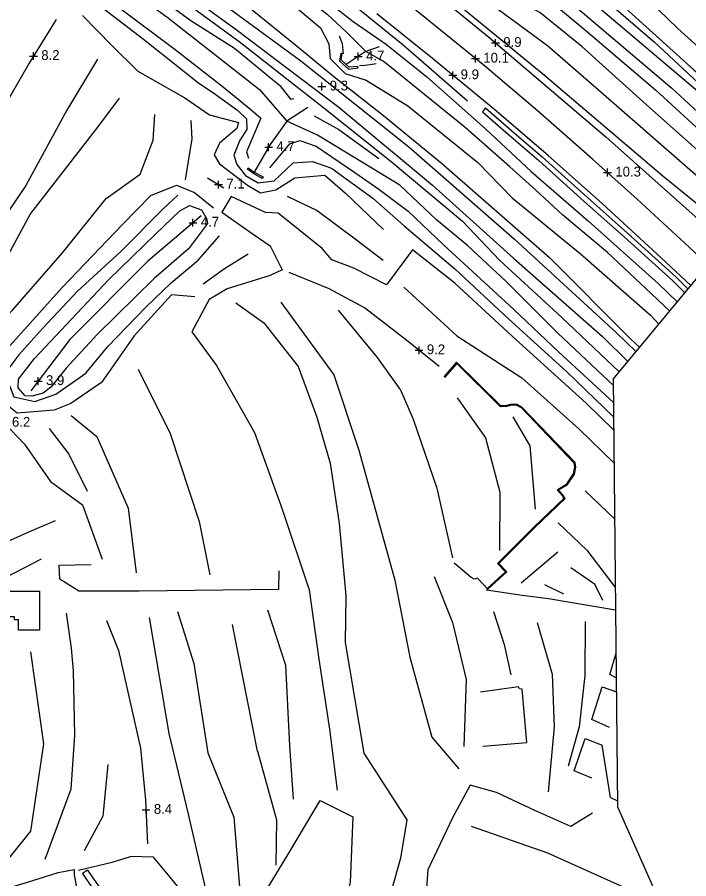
# Model space of a CAD drawing. Extents: x 2316231 to 2323598, y 363169 to 371906.
# Drawn here: x 2320503.7 to 2320845.6, y 365317.1 to 365756.1 of the extents above; entities that cross this region are included whole.
import ezdxf

# ---------------------------------------------------------------- set-up
doc = ezdxf.new("R2010")
doc.units = 0
for name, color, linetype in [('RD_DTM_BkLn1', 7, 'Continuous'), ('RD_DTM_TinHull', 7, 'Continuous'), ('RD_DTM_Void', 7, 'Continuous'), ('RD_EX_H2O', 7, 'Continuous'), ('RD_EX_Road', 7, 'Continuous')]:
    doc.layers.add(name, color=color, linetype=linetype)

msp = doc.modelspace()

# ---------------------------------------------------------------- linework, layer by layer
at = {"layer": 'RD_DTM_BkLn1'}
for p, q in [((2320600.584, 365674.209), (2320608.887, 365669.095)), ((2320778.886, 365483.504), (2320760.207, 365467.735)), ((2320781.977, 365462.194), (2320772.252, 365466.971)), ((2320626.054, 365382.15), (2320613.359, 365446.643)), ((2320732.239, 365418.613), (2320731.107, 365384.51)), ((2320789.848, 365394.629), (2320784.128, 365374.551)), ((2320805.686, 365358.613), (2320801.488, 365385.269)), ((2320805.686, 365358.613), (2320809.333, 365356.823))]:
    msp.add_line(p, q, dxfattribs=at)
for points in [[(2320125.425, 366145.994), (2320161.294, 366129.015), (2320184.806, 366118.194), (2320219.268, 366097.334), (2320257.75, 366078.61), (2320301.401, 366053.593), (2320339.6, 366032.049), (2320388.854, 366006.136), (2320433.491, 365980.54), (2320471.094, 365961.437), (2320509.936, 365935.57), (2320558.33, 365906.04), (2320596.656, 365879.53), (2320637.36, 365850.344), (2320679.307, 365816.521), (2320703.841, 365798.525), (2320711.978, 365788.521), (2320716.795, 365779.622), (2320731.36, 365769.609), (2320746.226, 365761.92), (2320773.664, 365741.714), (2320802.121, 365716.946), (2320848.849, 365676.056), (2320875.469, 365654.227)], [(2320183.14, 366148.693), (2320239.09, 366117.639), (2320296.494, 366085.739), (2320349.802, 366055.132), (2320405.378, 366025.418), (2320448.083, 365999.362), (2320490.768, 365974.618), (2320559.324, 365931.873), (2320617.279, 365892.959), (2320678.148, 365848.809), (2320727.47, 365811.314), (2320779.04, 365769.194), (2320836.996, 365719.869), (2320889.686, 365671.382)], [(2320182.737, 366143.817), (2320231.045, 366116.001), (2320278.866, 366087.979), (2320328.405, 366059.321), (2320373.611, 366034.853), (2320417.281, 366010.392), (2320460.243, 365986.01), (2320498.805, 365963.232), (2320547.113, 365932.568), (2320590.276, 365902.488), (2320625.131, 365879.992), (2320670.35, 365847.996), (2320704.214, 365820.962), (2320721.604, 365807.145), (2320731.665, 365799.894), (2320745.055, 365790.38), (2320759.08, 365777.797), (2320794.333, 365748.347), (2320828.782, 365718.919), (2320859.537, 365690.73), (2320885.477, 365666.303)], [(2320232.419, 366129.527), (2320276.765, 366104.361), (2320326.97, 366076.072), (2320377.845, 366047.504), (2320438.873, 366013.35), (2320491.432, 365981.475), (2320553.439, 365943.338), (2320618.359, 365900.899), (2320682.218, 365854.928), (2320740.085, 365810.827), (2320800.745, 365760.357), (2320857.803, 365711.976), (2320894.516, 365677.21)], [(2320320.221, 366098.87), (2320343.73, 366084.834), (2320356.505, 366077.219), (2320384.555, 366059.676), (2320419.447, 366040.181), (2320447.866, 366021.901), (2320471.868, 366008.615), (2320488.936, 365996.515), (2320514.303, 365982.74), (2320529.316, 365972.626), (2320554.954, 365955.917), (2320587.739, 365935.149), (2320612.576, 365918.662), (2320641.664, 365897.147), (2320678.381, 365870.456), (2320716.77, 365840.459), (2320734.571, 365828.326), (2320756.632, 365810.066), (2320790.938, 365779.493), (2320809.818, 365763.92), (2320848.173, 365729.232), (2320863.138, 365716.2), (2320899.36, 365685.757), (2320900.62, 365684.576)], [(2320315.308, 366088.614), (2320345.863, 366070.993), (2320387.782, 366047.357), (2320430.265, 366024.388), (2320470.415, 366003.883), (2320504.878, 365981.214), (2320529.854, 365965.458), (2320578.485, 365933.231), (2320618.03, 365906.824), (2320639.032, 365893.635), (2320675.308, 365866.642), (2320706.175, 365841.844), (2320753.882, 365805.574), (2320792.936, 365773.891), (2320828.235, 365743.377), (2320879.989, 365695.168), (2320896.418, 365679.505)], [(2320855.357, 365629.958), (2320845.868, 365638.904), (2320819.287, 365663.389), (2320796.672, 365683.748), (2320768.394, 365708.644), (2320741.53, 365731.29), (2320709.31, 365757.523), (2320675.444, 365784.438), (2320645.131, 365807.256), (2320627.321, 365820.5), (2320607.968, 365835.099), (2320591.031, 365846.394), (2320569.199, 365861.189), (2320543.695, 365879.161)], [(2320602.629, 365865.677), (2320641.904, 365832.75), (2320690.389, 365794.379), (2320722.377, 365767.546), (2320771.111, 365727.387), (2320832.413, 365675.302), (2320868.558, 365645.887)], [(2320505.475, 365856.979), (2320520.864, 365848.587), (2320545.172, 365833.324), (2320574.899, 365813.74), (2320610.258, 365787.16), (2320641.215, 365764.842), (2320658.117, 365750.723), (2320662.317, 365742.611), (2320663.086, 365735.015), (2320670.708, 365727.381), (2320681.36, 365723.951), (2320702.529, 365710.89), (2320738.215, 365682.049), (2320755.731, 365664.117), (2320790.277, 365635.787), (2320826.19, 365604.332), (2320830.311, 365599.735)], [(2320531.154, 365854.994), (2320562.66, 365836.912), (2320593.866, 365815.631), (2320622.996, 365793.667), (2320657.616, 365767.534), (2320674.76, 365753.896), (2320691.644, 365742.188), (2320712.309, 365725.73), (2320742.067, 365699.137), (2320765.35, 365677.399), (2320794.487, 365652.244), (2320830.03, 365620.462), (2320839.699, 365611.064)], [(2320494.756, 365849.313), (2320517.539, 365834.967), (2320560.151, 365809.006), (2320603.795, 365775.848), (2320645.456, 365741.875), (2320664.804, 365725.847), (2320689.325, 365706.764), (2320719.517, 365681.82), (2320774.711, 365633.699), (2320816.181, 365591.988), (2320820.585, 365587.999)], [(2320487.964, 365837.237), (2320513.325, 365820.129), (2320563.533, 365787.35), (2320615.078, 365749.886), (2320667.434, 365710.191), (2320715.063, 365670.543), (2320756.33, 365633.36), (2320801.65, 365593.339), (2320814.522, 365580.683)], [(2320495.801, 365839.314), (2320540.146, 365810.177), (2320599.875, 365769.409), (2320648.098, 365733.83), (2320703.015, 365690.061), (2320756.957, 365642.96), (2320808.871, 365595.211), (2320818.714, 365585.741)], [(2320485.487, 365833.622), (2320504.647, 365821.714), (2320535.41, 365801.833), (2320578.386, 365771.968), (2320617.431, 365743.287), (2320659.726, 365709.98), (2320694.071, 365682.621), (2320730.364, 365652.213), (2320749.321, 365632.325), (2320781.055, 365603.107), (2320810.117, 365575.367)], [(2320475.372, 365817.646), (2320481.696, 365821.632), (2320490.565, 365819.23), (2320505.711, 365810.344), (2320515.374, 365806.23), (2320528.128, 365799.749), (2320560.904, 365777.338), (2320592.16, 365754.331), (2320614.238, 365740.301), (2320637.32, 365721.378), (2320642.869, 365714.337), (2320644.444, 365714.613)], [(2320503.28, 365801.995), (2320525.612, 365785.54), (2320553.699, 365762.395), (2320584.774, 365739.166), (2320608.674, 365720.434), (2320622.584, 365709.046), (2320627.658, 365704.681), (2320620.473, 365687.552), (2320621.449, 365684.302)], [(2320654.91, 365777.105), (2320675.289, 365762.269), (2320700.245, 365742.034), (2320733.027, 365713.442)], [(2320529.506, 365774.584), (2320568.018, 365744.987), (2320596.148, 365722.409), (2320603.158, 365717.855), (2320615.924, 365708.55), (2320620.421, 365704.275), (2320620.673, 365698.871), (2320617.061, 365693.515), (2320613.976, 365685.872), (2320615.547, 365681.031), (2320619.981, 365675.493), (2320626.421, 365671.631), (2320634.495, 365672.772), (2320644.192, 365681.869), (2320653.963, 365682.658), (2320663.621, 365679.123), (2320684.68, 365663.888), (2320700.755, 365649.791), (2320726.506, 365627.952), (2320753.748, 365602.43), (2320783.313, 365575.509), (2320807.356, 365552.509)], [(2320523.577, 365754.875), (2320509.688, 365732.7), (2320480.808, 365682.431), (2320463.932, 365647.223), (2320445.882, 365607.764), (2320437.102, 365579.238), (2320429.956, 365530.993)], [(2320669.78, 365737.354), (2320669.371, 365742.512), (2320667.813, 365746.431)], [(2320544.633, 365734.641), (2320528.996, 365708.742), (2320508.038, 365670.288), (2320481.592, 365631.346), (2320476.782, 365614.234), (2320488.614, 365593.43), (2320501.486, 365606.991), (2320526.676, 365636.128), (2320548.952, 365663.705), (2320566.206, 365676.089), (2320572.957, 365693.495), (2320573.77, 365706.579)], [(2320686.439, 365732.279), (2320683.468, 365731.89), (2320680.626, 365731.406), (2320678.014, 365731.402)], [(2320555.508, 365714.842), (2320544.595, 365700.134), (2320510.509, 365656.052), (2320487.171, 365613.325)], [(2320654.935, 365705.796), (2320667.447, 365698.893), (2320687.755, 365684.07)], [(2320592.037, 365703.504), (2320592.604, 365693.949), (2320591.477, 365686.955), (2320589.121, 365673.299)], [(2320632.342, 365679.274), (2320642.504, 365691.545), (2320647.606, 365693.195), (2320655.961, 365690.385), (2320675.529, 365676.895), (2320687.857, 365668.493), (2320702.655, 365657.224), (2320720.725, 365640.16), (2320756.584, 365607.134), (2320779.29, 365585.639), (2320807.283, 365559.748)], [(2320585.385, 365665.499), (2320577.885, 365658.229), (2320556.418, 365636.81), (2320534.292, 365616.57), (2320516.697, 365597.643), (2320504.522, 365584.027), (2320497.433, 365574.637), (2320502.011, 365562.692), (2320512.57, 365560.303), (2320523.324, 365564.034), (2320538.619, 365574.788), (2320549.896, 365588.321), (2320569.229, 365608.324), (2320582.052, 365620.763), (2320595.857, 365632.327), (2320606.671, 365644.79)], [(2320641.145, 365664.925), (2320656.346, 365657.575), (2320676.463, 365642.647), (2320689.925, 365632.282)], [(2320600.555, 365650.952), (2320590.883, 365638.12), (2320573.394, 365622.986), (2320544.418, 365594.463), (2320528.664, 365577.287), (2320520.803, 365567.552), (2320516.818, 365564.505), (2320511.186, 365563.039), (2320507.713, 365563.117), (2320504.089, 365567.275), (2320504.321, 365571.644), (2320512.452, 365582.168), (2320550.307, 365622.457), (2320574.184, 365645.678), (2320586.502, 365657.472), (2320591.356, 365660.083), (2320597.581, 365657.89), (2320599.997, 365653.571), (2320600.555, 365650.952)], [(2320621.338, 365635.355), (2320609.18, 365627.895), (2320598.411, 365620.064)], [(2320718.466, 365578.11), (2320702.109, 365591.36), (2320680.513, 365608.054), (2320662.551, 365617.66), (2320642.069, 365626.081)], [(2320700.497, 365618.525), (2320727.441, 365593.74), (2320760.677, 365572.292), (2320789.569, 365546.372), (2320807.595, 365528.892)], [(2320614.91, 365610.629), (2320629.165, 365600.384), (2320646.722, 365578.161), (2320656.026, 365552.791), (2320663.046, 365528.951), (2320667.663, 365498.227), (2320670.918, 365461.504), (2320670.609, 365437.554), (2320680.119, 365381.089), (2320702.104, 365347.183)], [(2320637.827, 365610.829), (2320664.867, 365573.859), (2320677.699, 365535.552), (2320695.89, 365469.219), (2320703.524, 365430.126), (2320714.776, 365389.369), (2320728.556, 365373.232)], [(2320698.706, 365566.62), (2320687.088, 365582.706), (2320667.215, 365606.872)], [(2320592.623, 365595.722), (2320605.225, 365578.7), (2320624.488, 365544.426), (2320638.634, 365505.441), (2320652.316, 365464.288), (2320657.327, 365429.068), (2320662.604, 365393.396), (2320666.567, 365362.302)], [(2320565.209, 365576.715), (2320581.619, 365543.989), (2320596.237, 365499.125), (2320601.82, 365471.958)], [(2320698.706, 365566.62), (2320705.347, 365551.293), (2320717.365, 365516.069), (2320725.258, 365480.695)], [(2320448.075, 365556.909), (2320465.102, 365560.562), (2320481.208, 365559.511), (2320497.014, 365549.447), (2320507.384, 365538.552), (2320520.549, 365519.481), (2320536.911, 365507.637), (2320547.003, 365480.001)], [(2320727.722, 365562.148), (2320742.195, 365541.854), (2320749.366, 365514.076), (2320749.163, 365484.405)], [(2320531.084, 365553.243), (2320544.175, 365542.527), (2320560.136, 365505.966), (2320564.159, 365473.087)], [(2320756, 365552.496), (2320764.715, 365537.722), (2320767.341, 365505.498)], [(2320519.879, 365546.481), (2320529.904, 365533.439), (2320539.361, 365514.556)], [(2320792.888, 365514.836), (2320807.718, 365500.447), (2320807.884, 365500.219)], [(2320522.914, 365499.586), (2320509.013, 365493.59), (2320486.279, 365483.425), (2320471.127, 365472.8), (2320450.421, 365460.317), (2320433.9, 365443.127), (2320428.184, 365427.922)], [(2320779.19, 365498.473), (2320793.659, 365484.538), (2320808.236, 365465.389)], [(2320515.792, 365479.951), (2320502.827, 365473.222), (2320486.919, 365465.442), (2320456.095, 365433.716), (2320446.913, 365409.982), (2320444.677, 365397.541)], [(2320785.526, 365475.799), (2320797.559, 365467.449), (2320801.675, 365459.172)], [(2320716.004, 365471.143), (2320725.239, 365447.748), (2320732.239, 365418.613)], [(2320528.58, 365452.458), (2320531.102, 365434.7), (2320532.14, 365423.129), (2320532.761, 365390.363), (2320530.894, 365362.757), (2320517.663, 365326.936)], [(2320585.303, 365453.255), (2320593.627, 365426.892), (2320600.766, 365381.341), (2320614.021, 365348.595), (2320617.308, 365306.826)], [(2320631.167, 365454.174), (2320640.353, 365425.922), (2320642.231, 365384.904), (2320644.163, 365357.735)], [(2320746.212, 365453.231), (2320751.546, 365436.431), (2320755.066, 365421.048)], [(2320549.061, 365448.705), (2320555.229, 365433.431), (2320566.453, 365383.693), (2320569.019, 365357.143), (2320570.057, 365335.031)], [(2320570.932, 365450.325), (2320580.928, 365391.112), (2320590.781, 365349.995), (2320599.884, 365310.245)], [(2320768.42, 365447.685), (2320776.047, 365421.39), (2320777.156, 365394.61), (2320774.015, 365361.453)], [(2320792.83, 365448.245), (2320792.725, 365420.734), (2320789.848, 365394.629)], [(2320498.282, 365328.526), (2320500.334, 365328.486), (2320510.645, 365341.358), (2320517.236, 365385.888), (2320510.549, 365432.686)], [(2320626.054, 365382.15), (2320635.712, 365347.097), (2320635.331, 365324.057)], [(2320549.889, 365375.426), (2320547.186, 365349.023), (2320537.833, 365331.448)], [(2320674.49, 365348.675), (2320673.193, 365315.327), (2320661.106, 365267.911), (2320636.737, 365238.362), (2320617.592, 365218.332), (2320597.216, 365201.958), (2320583.909, 365195.257)], [(2320702.104, 365347.183), (2320698.836, 365327.571), (2320683.289, 365271.795), (2320671.837, 365252.734)], [(2320734.822, 365343.929), (2320773.699, 365330.294), (2320819.274, 365309.851), (2320830.914, 365305.203)], [(2320712.776, 365321.728), (2320710.102, 365285.088), (2320701, 365248.708), (2320685.638, 365228.785), (2320702.178, 365213.17), (2320713.355, 365203.459)]]:
    msp.add_lwpolyline(points, dxfattribs=at)
at = {"layer": 'RD_DTM_TinHull'}
msp.add_lwpolyline([(2322749.057, 368805.183), (2322437.788, 368637.943), (2322185.484, 368501.144), (2321988.712, 368397.613), (2321906.574, 368261.806), (2321814.258, 368125.896), (2321753.197, 367969.571), (2321734.081, 367792.897), (2321812.341, 367285.803), (2321826.603, 366879.552), (2321787.983, 366568.052), (2321665.825, 366287.064), (2321428.475, 366067.062), (2321222.139, 365846.682), (2320971.939, 365770.635), (2320807.161, 365571.8), (2320809.363, 365353.877), (2320991.706, 364942.038)], dxfattribs=at)
at = {"layer": 'RD_DTM_Void'}
for p, q in [((2320747.189, 365740.952), (2320747.189, 365744.952)), ((2320745.189, 365742.952), (2320749.189, 365742.952)), ((2320509.939, 365736.295), (2320513.939, 365736.295)), ((2320511.939, 365734.295), (2320511.939, 365738.295)), ((2320677.325, 365734.04), (2320677.325, 365738.04)), ((2320737.007, 365732.972), (2320737.007, 365736.972)), ((2320675.325, 365736.04), (2320679.325, 365736.04)), ((2320735.007, 365734.972), (2320739.007, 365734.972)), ((2320725.477, 365724.489), (2320725.477, 365728.489)), ((2320723.477, 365726.489), (2320727.477, 365726.489)), ((2320656.797, 365720.769), (2320660.797, 365720.769)), ((2320658.797, 365718.769), (2320658.797, 365722.769)), ((2320629.689, 365689.906), (2320633.689, 365689.906)), ((2320631.689, 365687.906), (2320631.689, 365691.906)), ((2320802.24, 365676.935), (2320806.24, 365676.935)), ((2320804.24, 365674.935), (2320804.24, 365678.935)), ((2320604.132, 365670.792), (2320608.132, 365670.792)), ((2320606.132, 365668.792), (2320606.132, 365672.792)), ((2320593.145, 365649.409), (2320593.145, 365653.409)), ((2320591.145, 365651.409), (2320595.145, 365651.409)), ((2320708.258, 365584.379), (2320708.258, 365588.379)), ((2320706.258, 365586.379), (2320710.258, 365586.379)), ((2320512.36, 365570.682), (2320516.36, 365570.682)), ((2320514.36, 365568.682), (2320514.36, 365572.682)), ((2320567.249, 365352.235), (2320571.249, 365352.235)), ((2320569.249, 365350.235), (2320569.249, 365354.235))]:
    msp.add_line(p, q, dxfattribs=at)
at = {"layer": 'RD_EX_H2O'}
for p, q in [((2320687.999, 365740.995), (2320681.202, 365738.547)), ((2320651.571, 365710.083), (2320640.945, 365703.207))]:
    msp.add_line(p, q, dxfattribs=at)
for points in [[(2320516.418, 365858.9), (2320520.609, 365856.673), (2320529.119, 365851.994), (2320533.137, 365850.113), (2320540.156, 365844.329), (2320553.262, 365836.686), (2320574.84, 365822.379), (2320604.794, 365801.078), (2320634.374, 365779.238), (2320661.487, 365757.618), (2320671.313, 365748.515), (2320681.202, 365738.547)], [(2320404.421, 365703.635), (2320417.803, 365731.607), (2320433.671, 365757.03), (2320449.595, 365781.283), (2320465.031, 365801.466), (2320472.758, 365810.812), (2320479.737, 365815.157), (2320484.217, 365819.072), (2320489.885, 365815.823), (2320499.751, 365809.969), (2320511.62, 365802.684), (2320524.233, 365795.389), (2320547.79, 365779.545), (2320579.835, 365756.292), (2320626.977, 365719.296), (2320640.945, 365703.207)], [(2320881.233, 365661.182), (2320857.755, 365681.643), (2320823.997, 365711.57), (2320791.11, 365741.192), (2320769.711, 365758.569), (2320758.117, 365765.095), (2320746.733, 365770.566), (2320742.906, 365777.385), (2320737.033, 365785.978), (2320726.404, 365790.317)], [(2320681.202, 365738.547), (2320680.924, 365738.447), (2320671.245, 365731.975)], [(2320835.864, 365606.435), (2320826.645, 365615.234), (2320804.168, 365636.253), (2320781.243, 365655.363), (2320767.491, 365668.072), (2320754.462, 365679.91), (2320731.843, 365699.949), (2320690.705, 365733.183), (2320687.771, 365734.886), (2320681.202, 365738.547)], [(2320640.945, 365703.207), (2320632.429, 365691.199), (2320624.379, 365677.119)], [(2320807.193, 365568.585), (2320802.088, 365573.35), (2320778.843, 365595.276), (2320752.661, 365621.517), (2320733.187, 365639.686), (2320717.102, 365652.897), (2320698.495, 365670.524), (2320656.564, 365696.074), (2320640.945, 365703.207)], [(2320597.27, 365654.942), (2320570.204, 365631.761), (2320530.416, 365591.945), (2320510.603, 365565.707)]]:
    msp.add_lwpolyline(points, dxfattribs=at)
at = {"layer": 'RD_EX_Road'}
for p, q in [((2320742.17, 365709.849), (2320740.505, 365707.942)), ((2320539.521, 365321.513), (2320536.958, 365319.752))]:
    msp.add_line(p, q, dxfattribs=at)
for points in [[(2320616.537, 365844.377), (2320652.389, 365817.861), (2320703.175, 365779.237), (2320743.767, 365745.857), (2320803.456, 365695.174), (2320850.363, 365653.116)], [(2320815.279, 365774.45), (2320839.973, 365750.403), (2320863.044, 365729.679), (2320883.572, 365711.072), (2320906.694, 365691.905)], [(2320536.896, 365757.016), (2320551.808, 365741.61), (2320565.047, 365728.576), (2320588.953, 365715.091), (2320601.619, 365706.33), (2320616.271, 365702.414), (2320615.56, 365699.386), (2320606.651, 365691.897), (2320603.907, 365685.952), (2320606.723, 365681.473), (2320620.923, 365670.602), (2320627.468, 365666.692), (2320635.357, 365668.119), (2320645.063, 365674.191), (2320660.256, 365675.668), (2320670.848, 365666.449), (2320690.176, 365647.927)], [(2320846.63, 365619.427), (2320831.585, 365633.574), (2320801.569, 365661.21), (2320774.11, 365685.458), (2320747.896, 365708.083), (2320715.128, 365734.985), (2320686.801, 365757.814)], [(2320668.375, 365737.667), (2320667.699, 365733.878), (2320672.373, 365729.625), (2320677.205, 365730.242), (2320677.039, 365731.05), (2320672.673, 365730.643), (2320668.653, 365734.333), (2320669.201, 365737.529), (2320668.375, 365737.667)], [(2320742.17, 365709.849), (2320755.479, 365698.226), (2320770.995, 365685.039), (2320794.049, 365664.158), (2320814.484, 365646.13), (2320839.014, 365623.774), (2320845.189, 365617.688)], [(2320740.505, 365707.942), (2320753.827, 365696.309), (2320769.325, 365683.136), (2320792.362, 365662.271), (2320812.794, 365644.245), (2320837.273, 365621.937), (2320843.568, 365615.731)], [(2320628.424, 365673.92), (2320623.937, 365676.389), (2320620.846, 365678.714), (2320621.351, 365679.425), (2320624.371, 365677.106), (2320628.832, 365674.687), (2320628.424, 365673.92)], [(2320594.157, 365613.607), (2320582.2, 365614.701), (2320563.185, 365593.724), (2320546.629, 365569.999), (2320530.956, 365559.309), (2320522.465, 365555.964), (2320503.631, 365554.342), (2320500.309, 365557.078), (2320491.807, 365568.115), (2320490.631, 365574.298), (2320498.423, 365586.953), (2320526.631, 365618.357), (2320557.199, 365650.405), (2320571.79, 365665.268), (2320584.759, 365670.472), (2320593.906, 365666.707), (2320603.594, 365658.893)], [(2320807.425, 365545.675), (2320793.333, 365559.409), (2320755.645, 365593.616), (2320726.448, 365620.568), (2320704.867, 365637.546), (2320691.753, 365619.758), (2320674.995, 365628.286), (2320663.938, 365632.441), (2320659, 365638.269), (2320636.557, 365656.298), (2320630.084, 365656.532), (2320612.649, 365664.796), (2320607.835, 365656.843), (2320623.24, 365645.981), (2320632.475, 365639.686), (2320638.537, 365627.332), (2320632.499, 365624.488), (2320610.588, 365617.752), (2320601.467, 365612.252), (2320592.623, 365595.722)], [(2320743.256, 365464.721), (2320752.973, 365473.511), (2320748.878, 365477.828), (2320767.054, 365495.896), (2320782.614, 365510.841), (2320781.9, 365512.316), (2320779.324, 365515.219), (2320783.896, 365517.975), (2320787.413, 365523.285), (2320788.072, 365526.893), (2320787.687, 365529.167), (2320760.692, 365557.439), (2320758.239, 365558.805), (2320756.242, 365558.865), (2320754.906, 365558.763), (2320752.854, 365558.221), (2320749.993, 365558.068), (2320727.415, 365580.423), (2320720.939, 365572.811)], [(2320742.921, 365465.092), (2320752.258, 365473.538), (2320748.18, 365477.838), (2320766.704, 365496.254), (2320782.006, 365510.95), (2320781.48, 365512.036), (2320778.551, 365515.337), (2320783.541, 365518.345), (2320786.939, 365523.476), (2320787.564, 365526.896), (2320787.219, 365528.932), (2320760.382, 365557.039), (2320758.102, 365558.308), (2320756.254, 365558.364), (2320754.989, 365558.268), (2320752.932, 365557.725), (2320749.798, 365557.557), (2320727.446, 365579.689), (2320721.32, 365572.487)], [(2320636.954, 365474.029), (2320636.778, 365464.601), (2320565.706, 365463.592), (2320534.981, 365463.714), (2320525.437, 365469.812), (2320525.089, 365476.978), (2320541.366, 365477.308)], [(2320743.256, 365464.721), (2320738.055, 365470.305), (2320736.312, 365469.854), (2320734.749, 365470.57), (2320726.167, 365478.004)], [(2320808.351, 365454.013), (2320774.239, 365459.692), (2320760.825, 365461.549), (2320742.61, 365464.127), (2320743.256, 365464.721)], [(2320497.543, 365463.741), (2320515.032, 365463.757), (2320515.05, 365443.859), (2320504.371, 365443.85), (2320504.367, 365449.028), (2320502.216, 365449.026), (2320502.215, 365450.558), (2320497.439, 365450.554)], [(2320808.699, 365419.561), (2320805.409, 365421.217), (2320808.573, 365432.08)], [(2320740.822, 365384.746), (2320763.168, 365386.56), (2320760.741, 365413.818), (2320759.489, 365413.94), (2320758.982, 365414.916), (2320739.567, 365412.178)], [(2320805.299, 365394.274), (2320796.261, 365398.31), (2320801.548, 365414.872), (2320808.771, 365412.417)], [(2320796.245, 365368.447), (2320787.203, 365372.152), (2320792.785, 365388.651), (2320801.488, 365385.269)], [(2320796.602, 365350.574), (2320785.624, 365343.759), (2320767.314, 365351.916), (2320747.74, 365361.164), (2320734.241, 365364.915), (2320725.371, 365348.173), (2320712.776, 365321.728)], [(2320610.165, 365282.833), (2320627.076, 365305.644), (2320642.435, 365331.039), (2320657.931, 365357.011), (2320674.49, 365348.675)], [(2320534.93, 365321.572), (2320551.973, 365325.544), (2320561.346, 365328.488)], [(2320610.165, 365282.833), (2320580.716, 365319.065), (2320573.029, 365328.154), (2320561.346, 365328.488)], [(2320502.638, 365313.551), (2320508.891, 365315.407), (2320524.504, 365320.389), (2320532.748, 365321.871), (2320532.691, 365319.189), (2320534.053, 365311.798), (2320538.19, 365303.309), (2320521.778, 365291.175), (2320519.875, 365288.068)], [(2320536.958, 365319.752), (2320542.256, 365312.043), (2320546.619, 365305.091), (2320543.99, 365304.028), (2320547.654, 365297.46), (2320550.309, 365298.751), (2320552.625, 365291.564), (2320554.22, 365283.514)], [(2320539.521, 365321.513), (2320544.856, 365313.751), (2320549.253, 365306.744), (2320550.069, 365307.274), (2320553.848, 365300.443), (2320552.932, 365299.935), (2320555.641, 365292.346), (2320557.271, 365284.118)]]:
    msp.add_lwpolyline(points, dxfattribs=at)

# ---------------------------------------------------------------- texts
at = {"layer": 'RD_DTM_Void'}
for s, p in [('9.9', (2320751.189, 365740.952)), ('8.2', (2320515.939, 365734.295)), ('4.7', (2320681.325, 365734.04)), ('10.1', (2320741.007, 365732.972)), ('9.9', (2320729.477, 365724.489)), ('9.3', (2320662.797, 365718.769)), ('4.7', (2320635.689, 365687.906)), ('10.3', (2320808.24, 365674.935)), ('7.1', (2320610.132, 365668.792)), ('4.7', (2320597.145, 365649.409)), ('9.2', (2320712.258, 365584.379)), ('3.9', (2320518.36, 365568.682)), ('6.2', (2320501.014, 365547.447)), ('8.4', (2320573.249, 365350.235))]:
    msp.add_text(s, height=5, dxfattribs=at).set_placement(p)

doc.saveas('drawing.dxf')
